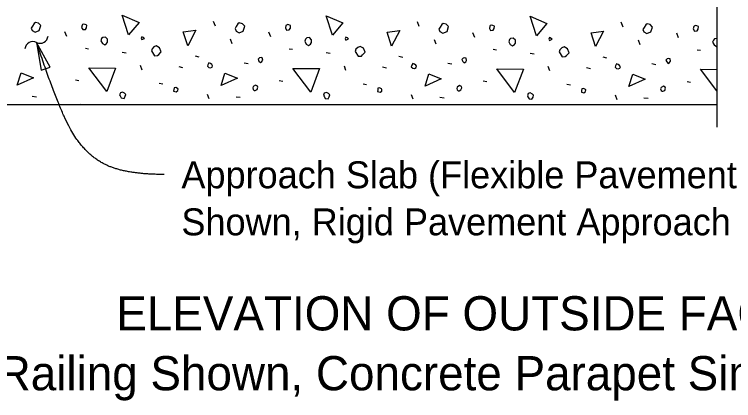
# Model space of a CAD drawing. Extents: x 0 to 72.1, y -15.2 to 30.1.
# Drawn here: x 10.77 to 16.14, y 12.94 to 15.83 of the extents above; entities that cross this region are included whole.
import ezdxf

# ---------------------------------------------------------------- set-up
doc = ezdxf.new("R2010")
doc.units = 0
for name, color, linetype in [('AdhocPoint_dp', 7, 'Continuous'), ('Patterning', 7, 'Continuous'), ('PlotBorder_dp', 7, 'Continuous')]:
    doc.layers.add(name, color=color, linetype=linetype)

msp = doc.modelspace()

# ---------------------------------------------------------------- linework, layer by layer
at = {"layer": 'AdhocPoint_dp'}
msp.add_line((16.018, 15.1533), (3.6311, 15.1533), dxfattribs=at)
at = {"layer": 'Patterning'}
for p, q in [((12.2703, 15.7432), (12.2562, 15.7786)), ((13.7941, 15.7397), (13.78, 15.775)), ((15.318, 15.7361), (15.3038, 15.7715)), ((11.1602, 15.6654), (11.146, 15.7008)), ((12.684, 15.6619), (12.6698, 15.6973)), ((12.3958, 15.6106), (12.3835, 15.6442)), ((14.2078, 15.6584), (14.1937, 15.6937)), ((15.7316, 15.6548), (15.7175, 15.6902)), ((13.9197, 15.6071), (13.9073, 15.6407)), ((15.4435, 15.6036), (15.4311, 15.6371)), ((11.2981, 15.577), (11.3228, 15.5735)), ((11.5738, 15.5488), (11.6039, 15.5435)), ((12.8219, 15.5735), (12.8466, 15.57)), ((13.0976, 15.5452), (13.1277, 15.5399)), ((14.3457, 15.57), (14.3704, 15.5664)), ((14.6215, 15.5417), (14.6515, 15.5364)), ((15.8695, 15.5664), (15.8943, 15.5629)), ((12.1183, 15.5205), (12.1466, 15.5134)), ((13.6421, 15.5169), (13.6704, 15.5099)), ((15.1659, 15.5134), (15.1942, 15.5063)), ((11.7223, 15.4144), (11.7099, 15.448)), ((11.9963, 15.4409), (12.0246, 15.4339)), ((12.4842, 15.4692), (12.5143, 15.4639)), ((13.2461, 15.4109), (13.2338, 15.4445)), ((13.5201, 15.4374), (13.5484, 15.4303)), ((14.008, 15.4657), (14.0381, 15.4604)), ((14.77, 15.4073), (14.7576, 15.4409)), ((15.044, 15.4339), (15.0722, 15.4268)), ((15.5319, 15.4621), (15.5619, 15.4568)), ((11.2238, 15.3402), (11.2503, 15.3349)), ((12.7476, 15.3366), (12.7741, 15.3313)), ((14.2714, 15.3331), (14.298, 15.3278)), ((15.7953, 15.3296), (15.8218, 15.3243)), ((11.8496, 15.3154), (11.8761, 15.3101)), ((13.3734, 15.3119), (13.3999, 15.3066)), ((14.8972, 15.3083), (14.9237, 15.303)), ((10.9003, 15.2182), (10.9321, 15.2147)), ((12.2244, 15.1987), (12.212, 15.2323)), ((12.4241, 15.2147), (12.4559, 15.2111)), ((13.7482, 15.1952), (13.7358, 15.2288)), ((15.272, 15.1917), (15.2596, 15.2253)), ((13.9479, 15.2111), (13.9798, 15.2076)), ((15.4718, 15.2076), (15.5036, 15.204))]:
    msp.add_line(p, q, dxfattribs=at)
for points in [[(11.6216, 15.6778), (11.5738, 15.8245), (11.6993, 15.7697), (11.6216, 15.6778)], [(13.1454, 15.6743), (13.0976, 15.821), (13.2232, 15.7662), (13.1454, 15.6743)], [(14.6692, 15.6707), (14.6215, 15.8175), (14.747, 15.7627), (14.6692, 15.6707)], [(10.9003, 15.7096), (10.9233, 15.6973), (10.9533, 15.7096), (10.9657, 15.7468), (10.948, 15.7644), (10.9251, 15.7697), (10.9145, 15.7627), (10.9021, 15.7432), (10.8932, 15.7273), (10.9003, 15.7096)], [(11.2698, 15.7326), (11.2786, 15.7167), (11.2981, 15.7185), (11.3069, 15.7308), (11.3087, 15.7503), (11.2963, 15.7556), (11.2875, 15.7574), (11.2768, 15.7538), (11.2733, 15.7503), (11.2698, 15.7326)], [(12.4241, 15.7061), (12.4471, 15.6937), (12.4772, 15.7061), (12.4895, 15.7432), (12.4719, 15.7609), (12.4489, 15.7662), (12.4383, 15.7591), (12.4259, 15.7397), (12.4171, 15.7238), (12.4241, 15.7061)], [(12.7936, 15.7291), (12.8024, 15.7132), (12.8219, 15.7149), (12.8307, 15.7273), (12.8325, 15.7468), (12.8201, 15.7521), (12.8113, 15.7538), (12.8007, 15.7503), (12.7971, 15.7468), (12.7936, 15.7291)], [(13.9479, 15.7026), (13.9709, 15.6902), (14.001, 15.7026), (14.0133, 15.7397), (13.9957, 15.7574), (13.9727, 15.7627), (13.9621, 15.7556), (13.9497, 15.7361), (13.9409, 15.7202), (13.9479, 15.7026)], [(14.3174, 15.7255), (14.3262, 15.7096), (14.3457, 15.7114), (14.3545, 15.7238), (14.3563, 15.7432), (14.3439, 15.7485), (14.3351, 15.7503), (14.3245, 15.7468), (14.3209, 15.7432), (14.3174, 15.7255)], [(15.4718, 15.699), (15.4947, 15.6866), (15.5248, 15.699), (15.5372, 15.7361), (15.5195, 15.7538), (15.4965, 15.7591), (15.4859, 15.7521), (15.4735, 15.7326), (15.4647, 15.7167), (15.4718, 15.699)], [(12.0635, 15.5965), (12.0299, 15.7008), (12.1236, 15.7132), (12.0635, 15.5965)], [(13.5873, 15.593), (13.5537, 15.6973), (13.6474, 15.7096), (13.5873, 15.593)], [(15.1111, 15.5894), (15.0775, 15.6937), (15.1712, 15.7061), (15.1111, 15.5894)], [(15.8412, 15.722), (15.8501, 15.7061), (15.8695, 15.7079), (15.8783, 15.7202), (15.8801, 15.7397), (15.8677, 15.745), (15.8589, 15.7468), (15.8483, 15.7432), (15.8448, 15.7397), (15.8412, 15.722)], [(11.4147, 15.6336), (11.4253, 15.6124), (11.443, 15.6018), (11.4572, 15.6124), (11.4642, 15.623), (11.4642, 15.6442), (11.4483, 15.6601), (11.4289, 15.6584), (11.42, 15.6495), (11.4147, 15.6336)], [(11.7206, 15.6425), (11.74, 15.6513), (11.7329, 15.6584), (11.7206, 15.6637), (11.7153, 15.6513), (11.7206, 15.6425)], [(12.9385, 15.6301), (12.9492, 15.6089), (12.9668, 15.5983), (12.981, 15.6089), (12.988, 15.6195), (12.988, 15.6407), (12.9721, 15.6566), (12.9527, 15.6548), (12.9438, 15.646), (12.9385, 15.6301)], [(13.2444, 15.6389), (13.2638, 15.6478), (13.2567, 15.6548), (13.2444, 15.6601), (13.2391, 15.6478), (13.2444, 15.6389)], [(14.4624, 15.6265), (14.473, 15.6053), (14.4906, 15.5947), (14.5048, 15.6053), (14.5119, 15.6159), (14.5119, 15.6371), (14.4959, 15.6531), (14.4765, 15.6513), (14.4677, 15.6425), (14.4624, 15.6265)], [(14.7682, 15.6354), (14.7876, 15.6442), (14.7806, 15.6513), (14.7682, 15.6566), (14.7629, 15.6442), (14.7682, 15.6354)], [(16.018, 15.6494), (16.0003, 15.6478), (15.9915, 15.6389), (15.9862, 15.623)], [(11.7913, 15.5576), (11.8142, 15.5205), (11.8372, 15.5222), (11.8461, 15.5311), (11.8655, 15.5505), (11.8531, 15.5806), (11.8284, 15.5947), (11.8107, 15.5877), (11.7966, 15.5735), (11.7913, 15.5576)], [(13.3151, 15.5541), (13.3381, 15.5169), (13.361, 15.5187), (13.3699, 15.5275), (13.3893, 15.547), (13.377, 15.577), (13.3522, 15.5912), (13.3345, 15.5841), (13.3204, 15.57), (13.3151, 15.5541)], [(15.9862, 15.623), (15.9968, 15.6018), (16.0145, 15.5912), (16.018, 15.5938)], [(14.8389, 15.5505), (14.8619, 15.5134), (14.8849, 15.5152), (14.8937, 15.524), (14.9131, 15.5435), (14.9008, 15.5735), (14.876, 15.5877), (14.8583, 15.5806), (14.8442, 15.5664), (14.8389, 15.5505)], [(12.5956, 15.4816), (12.6062, 15.471), (12.6168, 15.478), (12.6239, 15.4887), (12.6203, 15.5063), (12.6115, 15.5081), (12.5991, 15.5063), (12.5885, 15.4957), (12.5956, 15.4816)], [(14.1194, 15.478), (14.13, 15.4674), (14.1406, 15.4745), (14.1477, 15.4851), (14.1442, 15.5028), (14.1353, 15.5046), (14.1229, 15.5028), (14.1123, 15.4922), (14.1194, 15.478)], [(15.6432, 15.4745), (15.6538, 15.4639), (15.6644, 15.471), (15.6715, 15.4816), (15.668, 15.4993), (15.6591, 15.501), (15.6468, 15.4993), (15.6362, 15.4887), (15.6432, 15.4745)], [(11.4589, 15.2535), (11.3246, 15.4303), (11.5243, 15.4286), (11.4589, 15.2535)], [(12.2208, 15.4321), (12.2332, 15.4303), (12.2456, 15.4356), (12.2491, 15.4462), (12.2438, 15.4551), (12.2332, 15.4621), (12.2208, 15.4674), (12.2138, 15.4533), (12.2102, 15.4427), (12.2208, 15.4321)], [(13.7446, 15.4286), (13.757, 15.4268), (13.7694, 15.4321), (13.7729, 15.4427), (13.7676, 15.4515), (13.757, 15.4586), (13.7446, 15.4639), (13.7376, 15.4498), (13.734, 15.4392), (13.7446, 15.4286)], [(15.2685, 15.425), (15.2808, 15.4232), (15.2932, 15.4286), (15.2967, 15.4392), (15.2914, 15.448), (15.2808, 15.4551), (15.2685, 15.4604), (15.2614, 15.4462), (15.2579, 15.4356), (15.2685, 15.425)], [(10.7889, 15.3013), (10.8172, 15.3932), (10.9109, 15.3561), (10.7889, 15.3013)], [(12.3128, 15.2977), (12.341, 15.3897), (12.4347, 15.3525), (12.3128, 15.2977)], [(12.9827, 15.25), (12.8484, 15.4268), (13.0481, 15.425), (12.9827, 15.25)], [(13.8366, 15.2942), (13.8649, 15.3861), (13.9585, 15.349), (13.8366, 15.2942)], [(14.5066, 15.2465), (14.3722, 15.4232), (14.572, 15.4215), (14.5066, 15.2465)], [(15.3604, 15.2907), (15.3887, 15.3826), (15.4824, 15.3455), (15.3604, 15.2907)], [(16.018, 15.2592), (15.896, 15.4197), (16.018, 15.4186)], [(11.9574, 15.2571), (11.9769, 15.2518), (11.9893, 15.2606), (11.991, 15.273), (11.9875, 15.2765), (11.9733, 15.2836), (11.961, 15.2818), (11.9592, 15.2695), (11.9574, 15.2571)], [(12.5602, 15.2624), (12.5673, 15.2624), (12.5815, 15.2695), (12.5868, 15.2854), (12.585, 15.2942), (12.5708, 15.3013), (12.5532, 15.2907), (12.5496, 15.2801), (12.5532, 15.2695), (12.5602, 15.2624)], [(13.4812, 15.2535), (13.5007, 15.2482), (13.5131, 15.2571), (13.5148, 15.2695), (13.5113, 15.273), (13.4972, 15.2801), (13.4848, 15.2783), (13.483, 15.2659), (13.4812, 15.2535)], [(14.0841, 15.2588), (14.0911, 15.2588), (14.1053, 15.2659), (14.1106, 15.2818), (14.1088, 15.2907), (14.0947, 15.2977), (14.077, 15.2871), (14.0735, 15.2765), (14.077, 15.2659), (14.0841, 15.2588)], [(15.0051, 15.25), (15.0245, 15.2447), (15.0369, 15.2535), (15.0387, 15.2659), (15.0351, 15.2695), (15.021, 15.2765), (15.0086, 15.2748), (15.0068, 15.2624), (15.0051, 15.25)], [(15.6079, 15.2553), (15.6149, 15.2553), (15.6291, 15.2624), (15.6344, 15.2783), (15.6326, 15.2871), (15.6185, 15.2942), (15.6008, 15.2836), (15.5973, 15.273), (15.6008, 15.2624), (15.6079, 15.2553)], [(11.5579, 15.2217), (11.5668, 15.2058), (11.588, 15.2023), (11.5968, 15.2182), (11.6003, 15.2323), (11.5915, 15.2412), (11.5756, 15.25), (11.5597, 15.2447), (11.5544, 15.2288), (11.5579, 15.2217)], [(13.0817, 15.2182), (13.0906, 15.2023), (13.1118, 15.1987), (13.1206, 15.2147), (13.1242, 15.2288), (13.1153, 15.2376), (13.0994, 15.2465), (13.0835, 15.2412), (13.0782, 15.2253), (13.0817, 15.2182)], [(14.6055, 15.2147), (14.6144, 15.1987), (14.6356, 15.1952), (14.6444, 15.2111), (14.648, 15.2253), (14.6391, 15.2341), (14.6232, 15.2429), (14.6073, 15.2376), (14.602, 15.2217), (14.6055, 15.2147)], [(11.2825, 15.1533), (11.2821, 15.1545), (11.2592, 15.1563), (11.2582, 15.1533)]]:
    msp.add_lwpolyline(points, dxfattribs=at)
at = {"layer": 'PlotBorder_dp'}
msp.add_lwpolyline([(16.018, 19.2784), (16.018, 17.4276), (16.1214, 17.4276), (16.018, 17.3826), (15.9147, 17.3376), (16.018, 17.3376), (16.018, 14.9877)], dxfattribs=at)
msp.add_lwpolyline([(10.9339, 15.621), (10.9685, 15.4127), (11.0352, 15.4357)], close=True, dxfattribs=at)
for centre, start, end in [((10.9601, 15.6739), 243.2317, 354.9589), ((10.9064, 15.5675), 63.2317, 174.9589)]:
    msp.add_arc(centre, 0.0596, start, end, dxfattribs=at)
msp.add_open_spline([(11.8875, 14.6332), (11.6222, 14.6332), (11.3236, 14.7577), (11.108, 15.0898), (10.9339, 15.621)], degree=2, dxfattribs=at)

# ---------------------------------------------------------------- texts
for s, height, p in [('Approach Slab (Flexible Pavement Approach Slab ', 0.2016, (12.0159, 14.5298)), ('Shown, Rigid Pavement Approach Slab Similar)', 0.2016, (12.0159, 14.1778)), ('ELEVATION OF OUTSIDE FACE OF RAILING', 0.256001, (11.5294, 13.4666)), ('(Traffic Railing Shown, Concrete Parapet Similar) (See Note 3)', 0.256001, (9.4828, 13.0186))]:
    msp.add_text(s, height=height, dxfattribs=at).set_placement(p)

doc.saveas('drawing.dxf')
